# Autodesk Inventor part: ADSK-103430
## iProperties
Shininess: 0.0
Created: 2000-09
Part Number: ADSK-103430
Document SubType Name: Modeling
Stock Number: ADSK-103430
Density: 1 g/cm^3
Density: 0.0
Volumn: 0.0
Area: 0.0
PropertySet Name: Model Information
Control State: 0
Master: False
Checked Out: False
Author: gao
